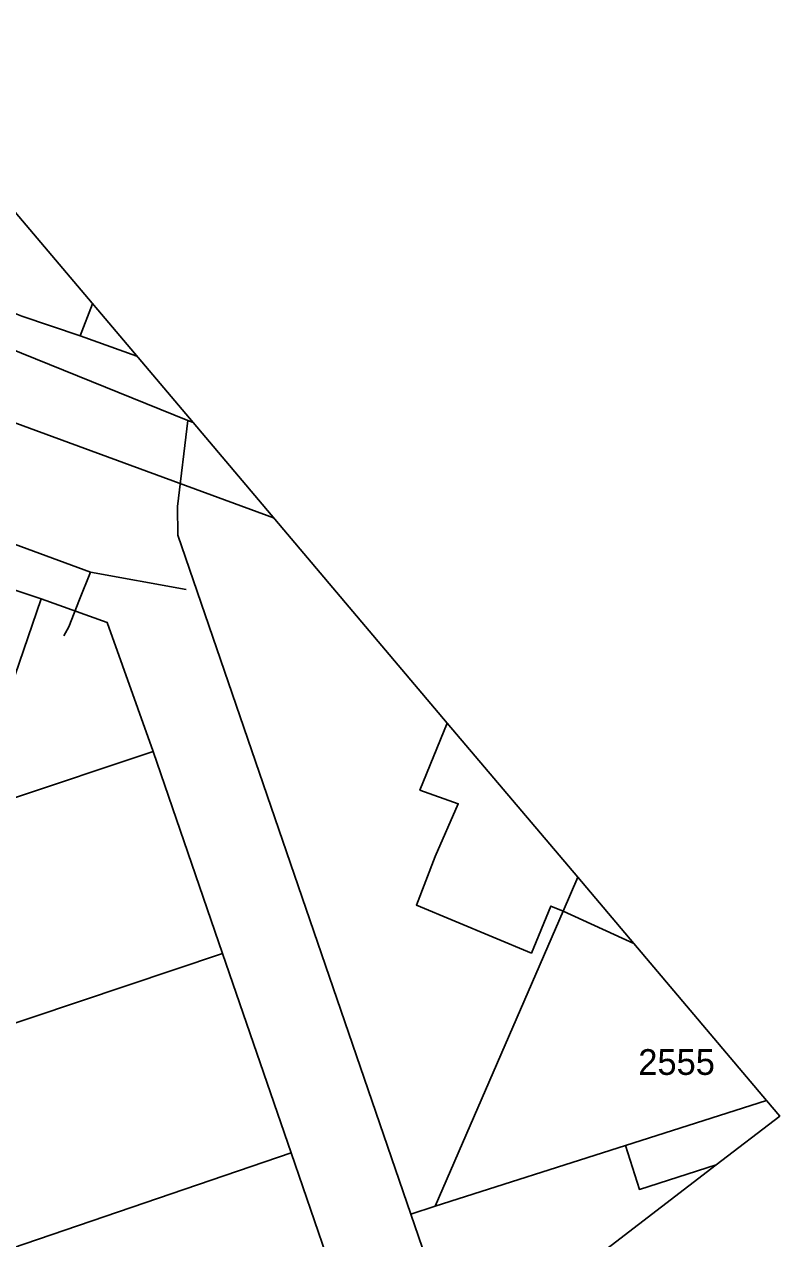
# Model space of a CAD drawing. Extents: x -570698 to -570232, y -1086952 to -1086596.
# Drawn here: x -570276.2 to -570232.2, y -1086766.4 to -1086695.6 of the extents above; entities that cross this region are included whole.
import ezdxf

# ---------------------------------------------------------------- set-up
doc = ezdxf.new("R2010")
doc.units = 0
for name, color, linetype in [('Kanalizační přípojka', 7, 'Continuous'), ('Kanalizační stoka', 7, 'Continuous'), ('Parcela-polygon', 7, 'Continuous'), ('Parcela-text', 7, 'Continuous'), ('Vodovodní přípojka', 7, 'Continuous'), ('Vodovodní řad', 7, 'Continuous')]:
    doc.layers.add(name, color=color, linetype=linetype)

msp = doc.modelspace()

# ---------------------------------------------------------------- linework, layer by layer
at = {"layer": 'Kanalizační přípojka'}
for points in [[(-570272.31, -1086727.54), (-570278.23, -1086725.35), (-570284.12, -1086723.235), (-570290.01, -1086721.12), (-570292.905, -1086718.705), (-570295.8, -1086716.29), (-570300.84, -1086714.11), (-570305.88, -1086711.93)], [(-570273.87, -1086731.24), (-570273.58, -1086730.72), (-570272.945, -1086729.13), (-570272.31, -1086727.54)], [(-570266.746, -1086728.544), (-570272.31, -1086727.54)]]:
    msp.add_lwpolyline(points, dxfattribs=at)
at = {"layer": 'Kanalizační stoka'}
msp.add_lwpolyline([(-570281.39, -1086717.12), (-570261.653, -1086724.356)], dxfattribs=at)
at = {"layer": 'Parcela-polygon'}
for p, q in [((-570266.341, -1086718.811), (-570282.287, -1086699.954)), ((-570251.533, -1086736.323), (-570266.341, -1086718.811)), ((-570243.93, -1086745.316), (-570251.533, -1086736.323)), ((-570240.663, -1086749.179), (-570243.93, -1086745.316)), ((-570232.934, -1086758.32), (-570240.663, -1086749.179)), ((-570248.969, -1086772.137), (-570235.863, -1086762.075))]:
    msp.add_line(p, q, dxfattribs=at)
for points in [[(-570282.287, -1086699.954), (-570284.51, -1086701.15), (-570285.82, -1086698.81), (-570286.13, -1086695.6), (-570301.2, -1086706.16), (-570299.67, -1086705.46), (-570295.46, -1086707.06), (-570284.42, -1086711.51), (-570266.64, -1086718.69), (-570266.341, -1086718.811)], [(-570250.717, -1086773.479), (-570250.86, -1086773.06), (-570250.95, -1086772.82), (-570253.65, -1086764.94), (-570267.22, -1086725.38), (-570267.25, -1086723.7), (-570266.64, -1086718.69), (-570284.42, -1086711.51), (-570289.55, -1086724.3), (-570275.18, -1086729.09), (-570271.35, -1086730.46), (-570268.66, -1086737.98), (-570264.62, -1086749.76), (-570260.63, -1086761.38), (-570256.55, -1086773.27), (-570255.281, -1086776.983)], [(-570266.341, -1086718.811), (-570266.64, -1086718.69), (-570267.25, -1086723.7), (-570267.22, -1086725.38), (-570253.65, -1086764.94), (-570252.23, -1086764.49), (-570244.78, -1086747.28), (-570245.49, -1086746.99), (-570246.63, -1086749.73), (-570253.33, -1086746.93), (-570252.24, -1086744.1), (-570250.89, -1086741.03), (-570253.12, -1086740.23), (-570251.533, -1086736.323)], [(-570251.533, -1086736.323), (-570253.12, -1086740.23), (-570250.89, -1086741.03), (-570252.24, -1086744.1), (-570253.33, -1086746.93), (-570246.63, -1086749.73), (-570245.49, -1086746.99), (-570244.78, -1086747.28), (-570243.93, -1086745.316)], [(-570243.93, -1086745.316), (-570244.78, -1086747.28), (-570240.663, -1086749.179)], [(-570240.663, -1086749.179), (-570244.78, -1086747.28), (-570252.23, -1086764.49), (-570241.14, -1086760.94), (-570232.934, -1086758.32)], [(-570232.934, -1086758.32), (-570241.14, -1086760.94), (-570240.33, -1086763.5), (-570235.863, -1086762.075)], [(-570235.863, -1086762.075), (-570232.162, -1086759.233), (-570232.934, -1086758.32)], [(-570235.863, -1086762.075), (-570240.33, -1086763.5), (-570241.14, -1086760.94), (-570252.23, -1086764.49), (-570253.65, -1086764.94), (-570250.95, -1086772.82), (-570249.24, -1086772.23), (-570248.969, -1086772.137)]]:
    msp.add_lwpolyline(points, dxfattribs=at)
for points in [[(-570289.55, -1086724.3), (-570292.35, -1086730.81), (-570290.38, -1086736.89), (-570287.94, -1086744.43), (-570285.65, -1086743.66), (-570289.32, -1086732.56), (-570288.11, -1086729.83), (-570285.02, -1086730.83), (-570286.19, -1086734.64), (-570278, -1086737.26), (-570275.18, -1086729.09)], [(-570268.66, -1086737.98), (-570271.35, -1086730.46), (-570275.18, -1086729.09), (-570278, -1086737.26), (-570286.19, -1086734.64), (-570285.02, -1086730.83), (-570288.11, -1086729.83), (-570289.32, -1086732.56), (-570285.65, -1086743.66)], [(-570302.3, -1086762.3), (-570298.08, -1086760.98), (-570264.62, -1086749.76), (-570268.66, -1086737.98), (-570285.65, -1086743.66), (-570287.94, -1086744.43), (-570308.21, -1086751.22), (-570312.02, -1086752.49), (-570309.51, -1086759.74), (-570305.56, -1086758.39), (-570303.99, -1086762.89)], [(-570260.63, -1086761.38), (-570264.62, -1086749.76), (-570298.08, -1086760.98), (-570296.2, -1086766.41), (-570294, -1086772.77)], [(-570256.55, -1086773.27), (-570260.63, -1086761.38), (-570294, -1086772.77), (-570299.95, -1086774.8), (-570296.28, -1086786.82), (-570295.2, -1086786.45), (-570283.82, -1086782.57), (-570265.5, -1086776.32), (-570259.26, -1086774.19)]]:
    msp.add_lwpolyline(points, close=True, dxfattribs=at)
at = {"layer": 'Vodovodní přípojka'}
msp.add_line((-570272.91, -1086713.76), (-570272.192, -1086711.891), dxfattribs=at)
at = {"layer": 'Vodovodní řad'}
msp.add_lwpolyline([(-570269.613, -1086714.942), (-570272.91, -1086713.76), (-570276.32, -1086712.62), (-570295.95, -1086704.77)], dxfattribs=at)

# ---------------------------------------------------------------- texts
at = {"layer": 'Parcela-text'}
msp.add_text('2555', height=1.5, dxfattribs=at).set_placement((-570240.4, -1086756.83))

doc.saveas('drawing.dxf')
